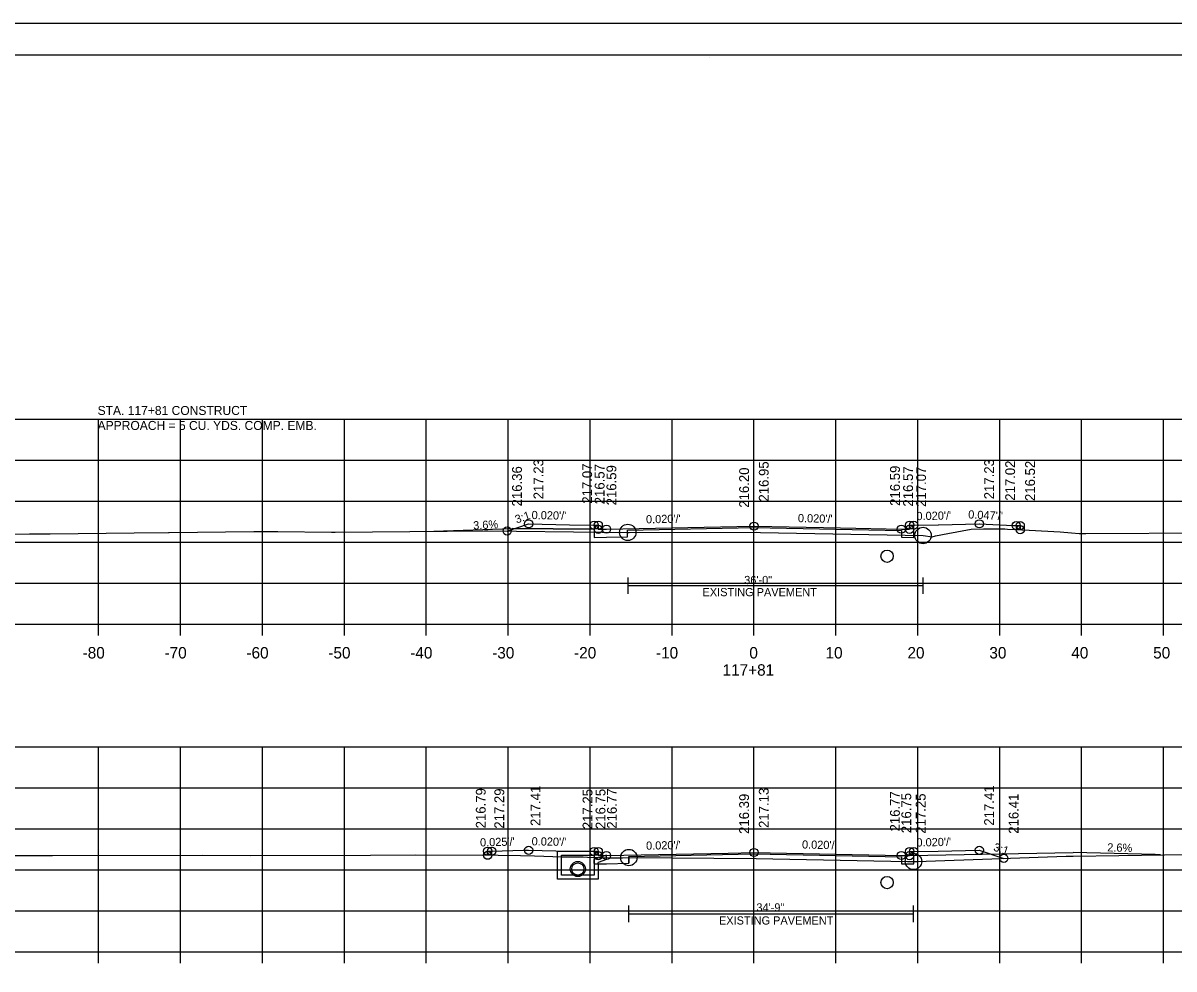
# Model space of a CAD drawing. Extents: x 1368968 to 1369915, y 377395 to 380381.
# Drawn here: x 1369662.5 to 1369803.1, y 379412.6 to 379528.1 of the extents above; entities that cross this region are included whole.
import ezdxf

# ---------------------------------------------------------------- set-up
doc = ezdxf.new("R2010")
doc.units = 0
for name, color, linetype in [('Default', 7, 'Continuous'), ('S_BORDER_NO_PLOT', 7, 'Continuous'), ('S_BREAKLINE_ANNOT', 7, 'Continuous'), ('S_BRIDGE', 7, 'Continuous'), ('S_BRIDGE_ANNOT', 7, 'Continuous'), ('S_CONTOUR_MINOR', 7, 'Continuous'), ('S_CROSS_DRAIN', 7, 'Continuous'), ('S_CTL_TABLE', 7, 'Continuous'), ('S_CURB_ANNOT', 7, 'Continuous'), ('S_DITCHLINE_ANNOT', 7, 'Continuous'), ('S_DROP_INLET', 7, 'Continuous'), ('S_EXIST_ROW_ANNOT', 7, 'Continuous'), ('S_EXISTING_ALIGNMENT_ANNOT', 7, 'Continuous'), ('S_FENCE', 7, 'Continuous')]:
    doc.layers.add(name, color=color, linetype=linetype)

msp = doc.modelspace()

# ---------------------------------------------------------------- linework, layer by layer
at = {"layer": 'Default'}
for p, q in [((1369712.69, 379466.05), (1369722.27, 379466.39)), ((1369722.27, 379466.39), (1369732.27, 379466.29)), ((1369769.78, 379466.14), (1369769.78, 379465.31)), ((1369784.29, 379466.74), (1369784.29, 379466.24)), ((1369736.51, 379426.37), (1369736.51, 379425.54)), ((1369769.78, 379426.32), (1369769.78, 379425.48))]:
    msp.add_line(p, q, dxfattribs=at)
for centre in [(1369768.03, 379463), (1369768.03, 379423.18)]:
    msp.add_circle(centre, 0.75, dxfattribs=at)
at = {"layer": 'S_BORDER_NO_PLOT'}
for points in [[(1369732.27, 379466.79), (1369732.28, 379465.28), (1369733.78, 379465.31), (1369736.35, 379465.36), (1369736.35, 379466.19), (1369751.78, 379466.5), (1369769.78, 379466.14), (1369769.78, 379465.31), (1369771.28, 379465.28), (1369771.29, 379466.79)], [(1369732.27, 379426.96), (1369732.28, 379425.45), (1369733.78, 379425.48), (1369736.51, 379425.54), (1369736.51, 379426.37), (1369751.78, 379426.67), (1369769.78, 379426.32), (1369769.78, 379425.48), (1369771.28, 379425.45), (1369771.29, 379426.96)]]:
    msp.add_lwpolyline(points, dxfattribs=at)
at = {"layer": 'S_BREAKLINE_ANNOT'}
for p, q in [((1369611.78, 379454.72), (1369891.78, 379454.72)), ((1369671.78, 379453.32), (1369671.78, 379454.72)), ((1369681.78, 379453.32), (1369681.78, 379454.72)), ((1369691.78, 379453.32), (1369691.78, 379454.72)), ((1369701.78, 379453.32), (1369701.78, 379454.72)), ((1369711.78, 379453.32), (1369711.78, 379454.72)), ((1369721.78, 379453.32), (1369721.78, 379454.72)), ((1369731.78, 379453.32), (1369731.78, 379454.72)), ((1369741.78, 379453.32), (1369741.78, 379454.72)), ((1369751.78, 379453.32), (1369751.78, 379454.72)), ((1369761.78, 379453.32), (1369761.78, 379454.72)), ((1369771.78, 379453.32), (1369771.78, 379454.72)), ((1369781.78, 379453.32), (1369781.78, 379454.72)), ((1369791.78, 379453.32), (1369791.78, 379454.72)), ((1369801.78, 379453.32), (1369801.78, 379454.72)), ((1369611.78, 379414.72), (1369891.78, 379414.72)), ((1369671.78, 379413.32), (1369671.78, 379414.72)), ((1369681.78, 379413.32), (1369681.78, 379414.72)), ((1369691.78, 379413.32), (1369691.78, 379414.72)), ((1369701.78, 379413.32), (1369701.78, 379414.72)), ((1369711.78, 379413.32), (1369711.78, 379414.72)), ((1369721.78, 379413.32), (1369721.78, 379414.72)), ((1369731.78, 379413.32), (1369731.78, 379414.72)), ((1369741.78, 379413.32), (1369741.78, 379414.72)), ((1369751.78, 379413.32), (1369751.78, 379414.72)), ((1369761.78, 379413.32), (1369761.78, 379414.72)), ((1369771.78, 379413.32), (1369771.78, 379414.72)), ((1369781.78, 379413.32), (1369781.78, 379414.72)), ((1369791.78, 379413.32), (1369791.78, 379414.72)), ((1369801.78, 379413.32), (1369801.78, 379414.72))]:
    msp.add_line(p, q, dxfattribs=at)
at = {"layer": 'S_BRIDGE_ANNOT'}
for p, q in [((1369593.78, 379524.18), (1369909.96, 379524.18)), ((1369746.3, 379523.92), (1369746.3, 379523.92)), ((1369746.3, 379523.92), (1369746.3, 379523.92))]:
    msp.add_line(p, q, dxfattribs=at)
at = {"layer": 'S_CROSS_DRAIN'}
for p, q in [((1369712.69, 379466.05), (1369722.27, 379466.39)), ((1369732.27, 379466.3), (1369722.27, 379466.39)), ((1369736.43, 379459.42), (1369772.42, 379459.42)), ((1369770.78, 379426.46), (1369790.77, 379426.86)), ((1369800.77, 379426.6), (1369790.77, 379426.86)), ((1369801.42, 379426.55), (1369800.77, 379426.6)), ((1369736.51, 379419.36), (1369771.26, 379419.36))]:
    msp.add_line(p, q, dxfattribs=at)
at = {"layer": 'S_CTL_TABLE'}
for points in [[(1369645.43, 379465.57), (1369663.33, 379465.74), (1369665.84, 379465.75), (1369676.13, 379465.87), (1369680.31, 379465.88), (1369680.4, 379465.88), (1369690.74, 379466), (1369690.97, 379466.01), (1369691.31, 379466.02), (1369693.66, 379466.01), (1369700.2, 379465.92), (1369700.64, 379465.93), (1369718.87, 379466.11), (1369718.94, 379466.11), (1369719.02, 379466.11), (1369719.05, 379466.11), (1369719.21, 379466.11), (1369719.3, 379466.11), (1369733.25, 379465.94), (1369736.26, 379465.91), (1369736.29, 379465.91), (1369736.31, 379465.91), (1369736.32, 379465.91), (1369736.38, 379465.91), (1369736.56, 379465.91), (1369752.09, 379465.92), (1369752.59, 379465.91), (1369772.42, 379465.53), (1369773.52, 379465.38), (1369773.94, 379465.47), (1369775.44, 379465.76), (1369778.28, 379466.31), (1369779.79, 379466.34), (1369781.79, 379466.36), (1369782.42, 379466.33), (1369782.75, 379466.32), (1369785.37, 379466.18), (1369789.16, 379465.98), (1369790.56, 379465.87), (1369791.5, 379465.79), (1369792.28, 379465.79), (1369807.74, 379465.87)], [(1369660.14, 379426.47), (1369662.84, 379426.47), (1369666.15, 379426.48), (1369684.42, 379426.5), (1369690.31, 379426.46), (1369704.95, 379426.53), (1369710.52, 379426.56), (1369720.55, 379426.51), (1369723.27, 379426.47), (1369725, 379426.42), (1369728.38, 379426.32), (1369730.94, 379426.3), (1369731.46, 379426.28), (1369734.05, 379426.21), (1369735.64, 379426.19), (1369735.75, 379426.19), (1369736.51, 379426.23), (1369746.87, 379426.15), (1369752.07, 379426.11), (1369770.52, 379425.76), (1369771.26, 379425.75), (1369771.67, 379425.76), (1369781.97, 379426.12), (1369789.9, 379426.38), (1369789.95, 379426.39), (1369790.02, 379426.39), (1369790.07, 379426.39), (1369790.17, 379426.39), (1369790.77, 379426.4), (1369813.06, 379426.72)]]:
    msp.add_lwpolyline(points, dxfattribs=at)
at = {"layer": 'S_CURB_ANNOT'}
for points in [[(1369721.65, 379466.08), (1369724.27, 379466.95), (1369724.27, 379466.95), (1369729.26, 379466.85), (1369729.27, 379466.85), (1369732.27, 379466.79), (1369732.27, 379466.79), (1369732.66, 379466.79), (1369732.77, 379466.79), (1369732.78, 379466.29), (1369733.77, 379466.31), (1369733.78, 379466.31), (1369751.68, 379466.67), (1369751.78, 379466.67), (1369751.88, 379466.67), (1369762.35, 379466.46), (1369769.78, 379466.31), (1369770.78, 379466.29), (1369770.79, 379466.79), (1369770.98, 379466.79), (1369771.29, 379466.79), (1369771.3, 379466.79), (1369774.29, 379466.85), (1369774.31, 379466.85), (1369779.29, 379466.95), (1369779.31, 379466.95), (1369783.42, 379466.76), (1369783.79, 379466.74), (1369784.29, 379466.74), (1369784.29, 379466.24)], [(1369719.27, 379426.51), (1369719.27, 379427.01), (1369719.77, 379427.01), (1369723.61, 379427.11), (1369724.27, 379427.12), (1369729.27, 379427.02), (1369732.27, 379426.96), (1369732.45, 379426.96), (1369732.77, 379426.96), (1369732.78, 379426.46), (1369733.78, 379426.48), (1369748.62, 379426.78), (1369751.78, 379426.84), (1369769.78, 379426.48), (1369770.78, 379426.46), (1369770.79, 379426.96), (1369771.17, 379426.96), (1369771.29, 379426.96), (1369774.29, 379427.02), (1369779.29, 379427.12), (1369782.28, 379426.13)]]:
    msp.add_lwpolyline(points, dxfattribs=at)
at = {"layer": 'S_DITCHLINE_ANNOT'}
for p, q in [((1369611.78, 379479.72), (1369891.78, 379479.72)), ((1369671.78, 379454.72), (1369671.78, 379479.72)), ((1369681.78, 379454.72), (1369681.78, 379479.72)), ((1369691.78, 379454.72), (1369691.78, 379479.72)), ((1369701.78, 379454.72), (1369701.78, 379479.72)), ((1369711.78, 379454.72), (1369711.78, 379479.72)), ((1369721.78, 379454.72), (1369721.78, 379479.72)), ((1369731.78, 379454.72), (1369731.78, 379479.72)), ((1369741.78, 379454.72), (1369741.78, 379479.72)), ((1369751.78, 379454.72), (1369751.78, 379479.72)), ((1369761.78, 379454.72), (1369761.78, 379479.72)), ((1369771.78, 379454.72), (1369771.78, 379479.72)), ((1369781.78, 379454.72), (1369781.78, 379479.72)), ((1369791.78, 379454.72), (1369791.78, 379479.72)), ((1369801.78, 379454.72), (1369801.78, 379479.72)), ((1369611.78, 379474.72), (1369891.78, 379474.72)), ((1369611.78, 379469.72), (1369891.78, 379469.72)), ((1369611.78, 379464.72), (1369891.78, 379464.72)), ((1369611.78, 379459.72), (1369891.78, 379459.72)), ((1369611.78, 379454.72), (1369891.78, 379454.72)), ((1369611.78, 379439.72), (1369891.78, 379439.72)), ((1369671.78, 379414.72), (1369671.78, 379439.72)), ((1369681.78, 379414.72), (1369681.78, 379439.72)), ((1369691.78, 379414.72), (1369691.78, 379439.72)), ((1369701.78, 379414.72), (1369701.78, 379439.72)), ((1369711.78, 379414.72), (1369711.78, 379439.72)), ((1369721.78, 379414.72), (1369721.78, 379439.72)), ((1369731.78, 379414.72), (1369731.78, 379439.72)), ((1369741.78, 379414.72), (1369741.78, 379439.72)), ((1369751.78, 379414.72), (1369751.78, 379439.72)), ((1369761.78, 379414.72), (1369761.78, 379439.72)), ((1369771.78, 379414.72), (1369771.78, 379439.72)), ((1369781.78, 379414.72), (1369781.78, 379439.72)), ((1369791.78, 379414.72), (1369791.78, 379439.72)), ((1369801.78, 379414.72), (1369801.78, 379439.72)), ((1369611.78, 379434.72), (1369891.78, 379434.72)), ((1369611.78, 379429.72), (1369891.78, 379429.72)), ((1369611.78, 379424.72), (1369891.78, 379424.72)), ((1369611.78, 379419.72), (1369891.78, 379419.72)), ((1369611.78, 379414.72), (1369891.78, 379414.72))]:
    msp.add_line(p, q, dxfattribs=at)
at = {"layer": 'S_DROP_INLET'}
for p, q in [((1369581.38, 379528.07), (1369914.71, 379528.07)), ((1369730.28, 379425.75), (1369730.28, 379425.74)), ((1369730.28, 379423.91), (1369730.28, 379423.9))]:
    msp.add_line(p, q, dxfattribs=at)
for points in [[(1369581.37, 379528.07), (1369914.71, 379528.07), (1369914.71, 379314.74), (1369581.37, 379314.74)], [(1369827.7, 379524.18), (1369827.7, 379514.3), (1369863.43, 379514.3), (1369863.43, 379511.38), (1369886.63, 379511.38), (1369886.63, 379487.05), (1369909.96, 379487.05), (1369909.96, 379318.72), (1369593.78, 379318.72), (1369593.78, 379524.18)]]:
    msp.add_lwpolyline(points, close=True, dxfattribs=at)
for centre, radius in [((1369724.27, 379466.95), 0.5), ((1369732.27, 379466.79), 0.5), ((1369732.77, 379466.79), 0.5), ((1369770.79, 379466.79), 0.5), ((1369771.29, 379466.79), 0.5), ((1369779.29, 379466.95), 0.5), ((1369783.79, 379466.74), 0.5), ((1369784.29, 379466.74), 0.5), ((1369721.65, 379466.08), 0.5), ((1369732.78, 379466.29), 0.5), ((1369733.78, 379466.31), 0.5), ((1369733.78, 379466.31), 0.5), ((1369736.38, 379465.91), 1), ((1369751.78, 379466.67), 0.5), ((1369769.78, 379466.31), 0.5), ((1369769.78, 379466.31), 0.5), ((1369770.78, 379466.29), 0.5), ((1369772.42, 379465.53), 1), ((1369784.29, 379466.24), 0.5), ((1369719.27, 379427.01), 0.5), ((1369719.27, 379426.51), 0.5), ((1369719.77, 379427.01), 0.5), ((1369724.27, 379427.12), 0.5), ((1369732.27, 379426.96), 0.5), ((1369732.77, 379426.96), 0.5), ((1369732.78, 379426.46), 0.5), ((1369733.78, 379426.48), 0.5), ((1369733.78, 379426.48), 0.5), ((1369736.51, 379426.23), 1), ((1369751.78, 379426.84), 0.5), ((1369769.78, 379426.48), 0.5), ((1369769.78, 379426.48), 0.5), ((1369771.26, 379425.75), 1), ((1369770.78, 379426.46), 0.5), ((1369770.79, 379426.96), 0.5), ((1369771.29, 379426.96), 0.5), ((1369779.29, 379427.12), 0.5), ((1369782.28, 379426.13), 0.5), ((1369730.28, 379424.83), 0.917)]:
    msp.add_circle(centre, radius, dxfattribs=at)
at = {"layer": 'S_EXIST_ROW_ANNOT'}
for p, q in [((1369736.43, 379458.42), (1369736.43, 379460.42)), ((1369772.42, 379458.42), (1369772.42, 379460.42)), ((1369727.78, 379427), (1369732.53, 379427)), ((1369727.78, 379425.5), (1369727.78, 379427)), ((1369728.28, 379425.5), (1369728.28, 379426.5)), ((1369728.28, 379426.5), (1369732.28, 379426.5)), ((1369732.61, 379426.83), (1369732.28, 379426.5)), ((1369733.78, 379426.52), (1369732.28, 379426)), ((1369732.61, 379426.83), (1369732.53, 379427)), ((1369730.28, 379425.58), (1369730.28, 379425.57)), ((1369732.28, 379425.5), (1369732.28, 379426)), ((1369733.78, 379425.99), (1369732.78, 379425.64)), ((1369732.78, 379425.5), (1369732.78, 379425.64)), ((1369730.28, 379424.08), (1369730.28, 379424.07)), ((1369736.51, 379418.36), (1369736.51, 379420.36)), ((1369771.26, 379418.36), (1369771.26, 379420.36))]:
    msp.add_line(p, q, dxfattribs=at)
for points in [[(1369733.78, 379425.99), (1369733.78, 379426.52)], [(1369732.78, 379425.5), (1369732.78, 379423.58), (1369730.28, 379423.58), (1369727.78, 379423.58), (1369727.78, 379425.5)], [(1369732.28, 379425.5), (1369732.28, 379424.08), (1369730.28, 379424.08), (1369728.28, 379424.08), (1369728.28, 379425.5)]]:
    msp.add_lwpolyline(points, dxfattribs=at)
msp.add_circle((1369730.28, 379424.83), 0.75, dxfattribs=at)
at = {"layer": 'S_EXISTING_ALIGNMENT_ANNOT'}
for p, q in [((1369751.78, 379465.92), (1369751.78, 379475.92)), ((1369751.78, 379426.11), (1369751.78, 379436.11))]:
    msp.add_line(p, q, dxfattribs=at)

# ---------------------------------------------------------------- texts
at = {"layer": 'S_BRIDGE'}
for s, p in [('-80', (1369669.82, 379450.52)), ('-70', (1369679.82, 379450.52)), ('-60', (1369689.82, 379450.52)), ('-50', (1369699.82, 379450.52)), ('-40', (1369709.82, 379450.52)), ('-30', (1369719.82, 379450.52)), ('-20', (1369729.82, 379450.52)), ('-10', (1369739.82, 379450.52)), ('0', (1369751.22, 379450.52)), ('10', (1369760.52, 379450.52)), ('20', (1369770.52, 379450.52)), ('30', (1369780.52, 379450.52)), ('40', (1369790.52, 379450.52)), ('50', (1369800.52, 379450.52)), ('117+81', (1369747.95, 379448.42))]:
    msp.add_text(s, height=1.4, dxfattribs=at).set_placement(p)
at = {"layer": 'S_CONTOUR_MINOR'}
for s, p in [('STA. 117+81 CONSTRUCT ', (1369671.65, 379480.24)), ('APPROACH = 5 CU. YDS. COMP. EMB.', (1369671.65, 379478.41))]:
    msp.add_text(s, height=1.1, dxfattribs=at).set_placement(p)
at = {"layer": 'S_CROSS_DRAIN'}
for s, rotation, p in [('3.6%', 3.2052, (1369717.53, 379466.26)), ('2.6%', 358.5106, (1369794.91, 379426.98))]:
    msp.add_text(s, height=1, rotation=rotation, dxfattribs=at).set_placement(p)
at = {"layer": 'S_EXIST_ROW_ANNOT'}
for s, p in [('36\'-0"', (1369750.59, 379459.6)), ('EXISTING PAVEMENT', (1369745.5, 379458.12)), ('34\'-9"', (1369752.08, 379419.64)), ('EXISTING PAVEMENT', (1369747.51, 379418.05))]:
    msp.add_text(s, height=1, dxfattribs=at).set_placement(p)
at = {"layer": 'S_EXISTING_ALIGNMENT_ANNOT'}
for s, p in [('217.23', (1369726.07, 379469.95)), ('217.07', (1369732.02, 379469.41)), ('216.95', (1369753.58, 379469.67)), ('217.23', (1369781.09, 379469.95)), ('217.02', (1369783.66, 379469.77)), ('216.52', (1369786.09, 379469.74)), ('216.36', (1369723.45, 379469.08)), ('216.57', (1369733.54, 379469.34)), ('216.59', (1369734.98, 379469.21)), ('216.20', (1369751.18, 379468.92)), ('216.59', (1369769.6, 379469.15)), ('216.57', (1369771.2, 379469.06)), ('217.07', (1369772.79, 379469.02)), ('217.41', (1369725.71, 379430.08)), ('217.41', (1369781.09, 379430.12)), ('216.79', (1369719.03, 379429.79)), ('217.29', (1369721.29, 379429.75)), ('217.25', (1369732.06, 379429.69)), ('216.75', (1369733.65, 379429.7)), ('216.77', (1369735.04, 379429.75)), ('216.39', (1369751.18, 379429.11)), ('217.13', (1369753.58, 379429.84)), ('216.77', (1369769.59, 379429.41)), ('216.75', (1369770.98, 379429.2)), ('217.25', (1369772.74, 379429.14)), ('216.41', (1369784.08, 379429.13))]:
    msp.add_text(s, height=1.2, rotation=90, dxfattribs=at).set_placement(p)
at = {"layer": 'S_FENCE'}
for s, rotation, p in [("0.047'/'", 357.2896, (1369777.92, 379467.62)), ('3:1', 18.4274, (1369722.8, 379466.99)), ("0.020'/'", 358.8543, (1369724.63, 379467.54)), ("0.020'/'", 1.1458, (1369738.61, 379467.01)), ("0.020'/'", 358.8543, (1369757.14, 379467.16)), ("0.020'/'", 1.1457, (1369771.63, 379467.4)), ("0.025'/'", 1.426, (1369718.35, 379427.58)), ("0.020'/'", 358.8543, (1369724.63, 379427.72)), ("0.020'/'", 1.1457, (1369738.62, 379427.18)), ("0.020'/'", 358.8542, (1369757.64, 379427.33)), ("0.020'/'", 1.1457, (1369771.63, 379427.57)), ('3:1', 341.5604, (1369780.94, 379427.1))]:
    msp.add_text(s, height=1, rotation=rotation, dxfattribs=at).set_placement(p)

doc.saveas('drawing.dxf')
